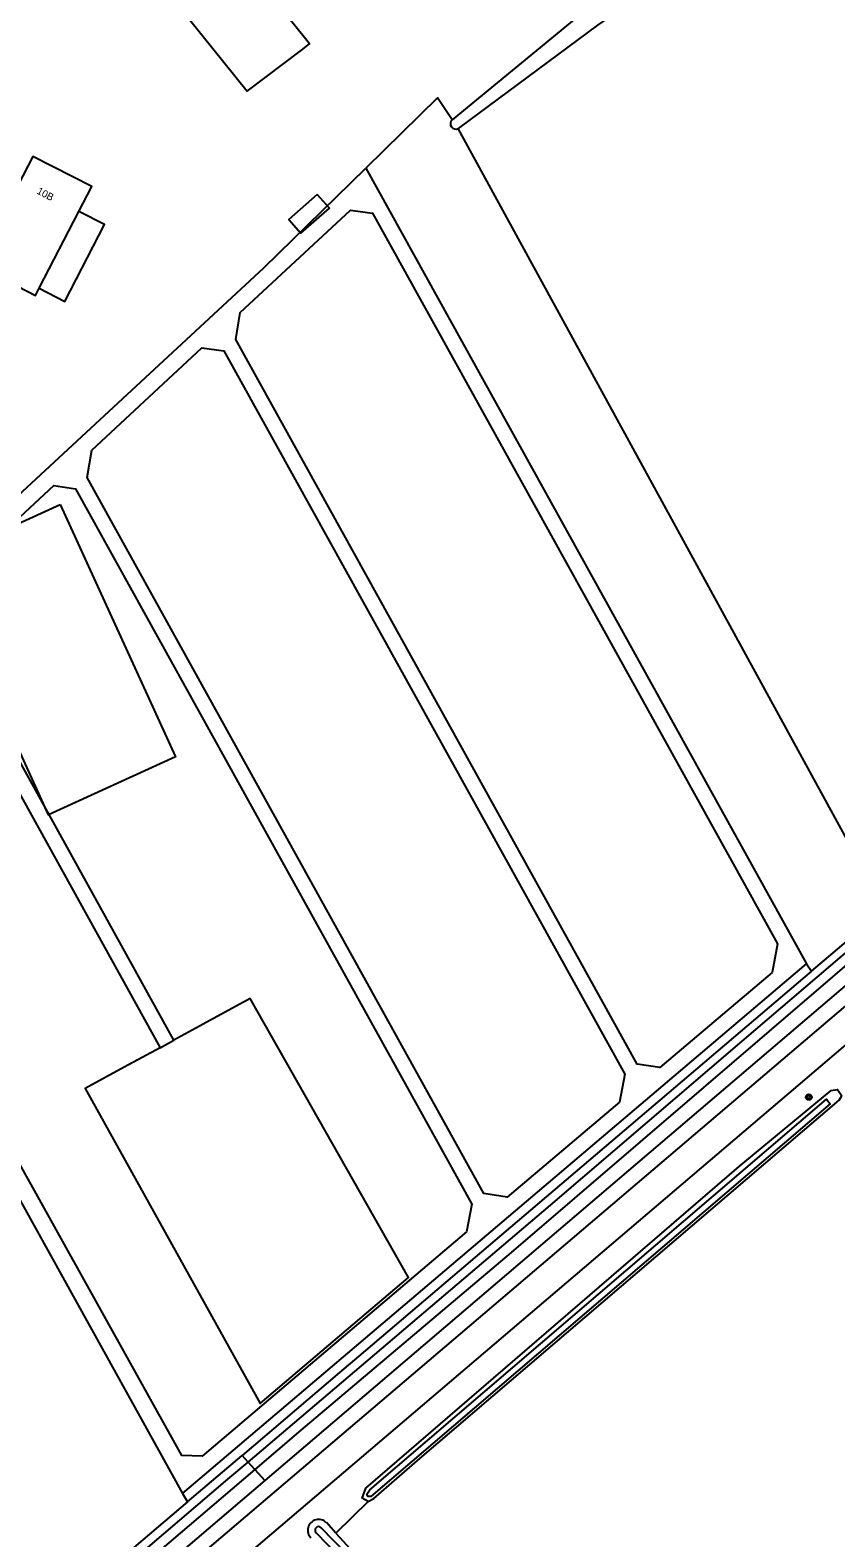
# Model space of a CAD drawing. Extents: x 141000 to 143000, y 400580 to 403500.
# Drawn here: x 141719.9 to 141831.6, y 402801.5 to 403010.7 of the extents above; entities that cross this region are included whole.
import ezdxf

# ---------------------------------------------------------------- set-up
doc = ezdxf.new("R2010")
doc.units = 0
for name, color, linetype in [('gg-anno-huisnummerreeks BGT', 7, 'Continuous'), ('gg-bbg-bassin', 7, 'Continuous'), ('gg-bbg-hoofdgebouw', 7, 'Continuous'), ('gg-bbg-luifel en loopbrug', 7, 'Continuous'), ('gg-knt-bronhoudergrens', 7, 'Continuous'), ('gg-knt-onverhard', 7, 'Continuous'), ('gg-knt-verharding', 7, 'Continuous'), ('gg-kntw-bovenkant insteek waterloop', 7, 'Continuous'), ('gg-kntw-waterlijn', 7, 'Continuous'), ('gt-bbg-plantopografie pand', 7, 'Continuous'), ('gt-grn-groengrens', 7, 'Continuous'), ('gt-grn-vlakafsluiter', 7, 'Continuous'), ('gt-symb-boom', 7, 'Continuous')]:
    doc.layers.add(name, color=color, linetype=linetype)

# ---------------------------------------------------------------- blocks, each defined once
blk = doc.blocks.new('gt0-BOOM')
at = {"layer": 'gt-symb-boom'}
for radius in [0.4, 0.2]:
    blk.add_circle((0, 0), radius, dxfattribs=at)

msp = doc.modelspace()

# ---------------------------------------------------------------- linework, layer by layer
at = {"layer": 'gg-bbg-bassin'}
msp.add_line((141737.88, 402869.52), (141739.81, 402870.58), dxfattribs=at)
msp.add_lwpolyline([(141737.88, 402869.52), (141732.88, 402866.81), (141727.49, 402863.88), (141751.76, 402820.16), (141772.33, 402837.65), (141750.4, 402876.34), (141743.87, 402872.79), (141739.81, 402870.58)], dxfattribs=at)
at = {"layer": 'gg-bbg-hoofdgebouw'}
msp.add_line((141721.12, 402974.87), (141726.62, 402985.52), dxfattribs=at)
for points in [[(141748.15, 403025.34), (141746.46, 403023.98), (141745.7, 403024.93), (141737.21, 403018.13), (141749.95, 403002.22), (141757.49, 403007.88), (141758.62, 403008.79), (141749.94, 403019.62), (141751.64, 403020.97), (141748.15, 403025.34)], [(141726.62, 402985.52), (141728.4, 402988.97), (141720.24, 402993.15), (141716.71, 402986.32), (141717.5, 402985.91), (141713.24, 402977.65), (141720.6, 402973.86), (141721.12, 402974.87)]]:
    msp.add_lwpolyline(points, dxfattribs=at)
at = {"layer": 'gg-bbg-luifel en loopbrug'}
for points in [[(141759.69, 402987.87), (141755.73, 402984.39), (141757.41, 402982.49), (141761.37, 402985.96), (141759.69, 402987.87)], [(141721.12, 402974.87), (141724.68, 402973.04), (141730.17, 402983.7), (141726.62, 402985.52)]]:
    msp.add_lwpolyline(points, dxfattribs=at)
at = {"layer": 'gg-knt-bronhoudergrens'}
msp.add_line((141838.43, 402888.78), (141779.26, 402997.04), dxfattribs=at)
msp.add_lwpolyline([(141778.4, 402998.24), (141776.37, 403001.29), (141766.41, 402991.54)], dxfattribs=at)
at = {"layer": 'gg-knt-onverhard'}
for p, q in [((141766.41, 402991.54), (141827.59, 402881.14)), ((141675.69, 402925.35), (141741.01, 402807.69)), ((141741.01, 402807.69), (141827.59, 402881.14)), ((141827.59, 402881.14), (141828.25, 402880.12)), ((141741.01, 402807.69), (141741.68, 402806.53))]:
    msp.add_line(p, q, dxfattribs=at)
for points in [[(141822.79, 402879.96), (141807.22, 402866.75), (141804.07, 402867.25), (141748.38, 402967.76), (141749, 402971.51), (141764.28, 402985.7), (141767.36, 402985.29), (141823.53, 402883.93), (141822.79, 402879.96)], [(141728.42, 402952.42), (141743.69, 402966.59), (141746.74, 402966.19), (141802.35, 402865.83), (141801.61, 402861.98), (141786.03, 402848.77), (141782.81, 402849.3), (141727.78, 402948.61), (141728.42, 402952.42)], [(141739.81, 402870.58), (141707.24, 402929.36), (141707.8, 402933.27), (141723.12, 402947.49), (141726.14, 402947.03), (141781.13, 402847.8), (141780.4, 402843.99), (141743.73, 402812.88), (141740.9, 402812.93), (141686.71, 402910.32), (141687.42, 402914.35), (141702.51, 402928.36), (141705.27, 402928.37), (141737.88, 402869.52)]]:
    msp.add_lwpolyline(points, dxfattribs=at)
at = {"layer": 'gg-knt-verharding'}
for p, q in [((141955.04, 402979.19), (141652.93, 402722.12)), ((141655.26, 402718.53), (141914.25, 402939.09))]:
    msp.add_line(p, q, dxfattribs=at)
msp.add_lwpolyline([(141715.59, 402943.74), (141752.27, 402977.7), (141766.41, 402991.54)], dxfattribs=at)
at = {"layer": 'gg-kntw-bovenkant insteek waterloop'}
for p, q in [((141879.18, 402917.54), (141752.42, 402809.49)), ((141828.25, 402880.12), (141837.5, 402887.99)), ((141741.68, 402806.53), (141749.25, 402812.96)), ((141741.68, 402806.53), (141724.57, 402791.99)), ((141762.27, 402802.17), (141760.95, 402803.64)), ((141762.27, 402802.17), (141768.88, 402794.95))]:
    msp.add_line(p, q, dxfattribs=at)
for points in [[(141759.07, 403082.75), (141772.3, 403061.67), (141794.03, 403019.91), (141796.66, 403014.85), (141797.39, 403013.53), (141796.67, 403013.2), (141796.37, 403012.96), (141778.4, 402998.24)], [(141800.04, 403012.39), (141798.59, 403011.34), (141779.26, 402997.04)], [(141828.25, 402880.12), (141765.46, 402826.74), (141762.77, 402824.46), (141749.25, 402812.96)], [(141766.76, 402806.55), (141765.9, 402807.03), (141766.43, 402808.44), (141818.23, 402853.06), (141831.01, 402863.57), (141831.86, 402863.7), (141832.48, 402862.85)], [(141766.76, 402806.55), (141767.55, 402806.99), (141773.9, 402812.52), (141832.12, 402862.23), (141832.48, 402862.85)], [(141752.42, 402809.49), (141651.15, 402723.16), (141647.88, 402726.79)]]:
    msp.add_lwpolyline(points, dxfattribs=at)
for centre, radius, start, end in [((141778.9, 402997.69), 0.745, 132.412, 298.6003), ((141759.88, 402802.58), 1.5, 44.7837, 224.7841)]:
    msp.add_arc(centre, radius, start, end, dxfattribs=at)
at = {"layer": 'gg-kntw-waterlijn'}
for points in [[(141750.09, 402812.04), (141792.04, 402847.68), (141818.62, 402870.43), (141841.36, 402889.82), (141862.6, 402907.71), (141876.69, 402919.86), (141876.21, 402920.89)], [(141878.05, 402918.98), (141865.9, 402908.68), (141840.3, 402887.18), (141786.58, 402841.13), (141757.42, 402816.47), (141751.02, 402811.02)], [(141767, 402808.19), (141830.33, 402862.37), (141830.84, 402861.75), (141767.12, 402807.28), (141766.77, 402807.28), (141766.59, 402807.59), (141767, 402808.19)], [(141649.64, 402728.29), (141650.44, 402727.34), (141666.44, 402740.75), (141701.28, 402770.41), (141747.3, 402809.66), (141750.09, 402812.04)], [(141751.02, 402811.02), (141731.56, 402794.43), (141699.3, 402766.85), (141667.77, 402740.38), (141650.92, 402725.34), (141650.63, 402725.22), (141650.25, 402725.31), (141649.87, 402725.59), (141649.5, 402726.04), (141649.63, 402726.49), (141648.82, 402727.59)], [(141962.98, 402594.95), (141963.15, 402595.12), (141963.56, 402595.47), (141953.19, 402606.06), (141897.64, 402662.45), (141865.12, 402695.32), (141819.82, 402740.64), (141797.37, 402763.16), (141787.22, 402773.68), (141759.53, 402802.23)], [(141965.29, 402596.83), (141964.32, 402596.12), (141953.55, 402607.09), (141929.52, 402631.16), (141910.62, 402650.17), (141898.35, 402663.15), (141865.83, 402696.03), (141817.14, 402744.39), (141797.61, 402764.11), (141788.13, 402774.31), (141760.24, 402802.94)]]:
    msp.add_lwpolyline(points, dxfattribs=at)
msp.add_arc((141759.88, 402802.58), 0.5, 44.8778, 224.7173, dxfattribs=at)
at = {"layer": 'gt-bbg-plantopografie pand'}
msp.add_lwpolyline([(141724.04, 402944.88), (141740.02, 402909.85), (141722.4, 402901.82), (141706.43, 402936.85), (141724.04, 402944.88)], dxfattribs=at)
at = {"layer": 'gt-grn-groengrens'}
msp.add_line((141766.76, 402806.55), (141762.27, 402802.17), dxfattribs=at)
at = {"layer": 'gt-grn-vlakafsluiter'}
for p, q in [((141750.09, 402812.04), (141749.25, 402812.96)), ((141751.02, 402811.02), (141750.09, 402812.04)), ((141751.02, 402811.02), (141752.42, 402809.49))]:
    msp.add_line(p, q, dxfattribs=at)

# ---------------------------------------------------------------- block references
at = {"layer": 'gt-symb-boom'}
msp.add_blockref('gt0-BOOM', (141827.89, 402862.67), dxfattribs=at)

# ---------------------------------------------------------------- texts
at = {"layer": 'gg-anno-huisnummerreeks BGT'}
msp.add_text('10B', height=1, rotation=332.7, dxfattribs=at).set_placement((141720.69, 402988.03))

doc.saveas('drawing.dxf')
